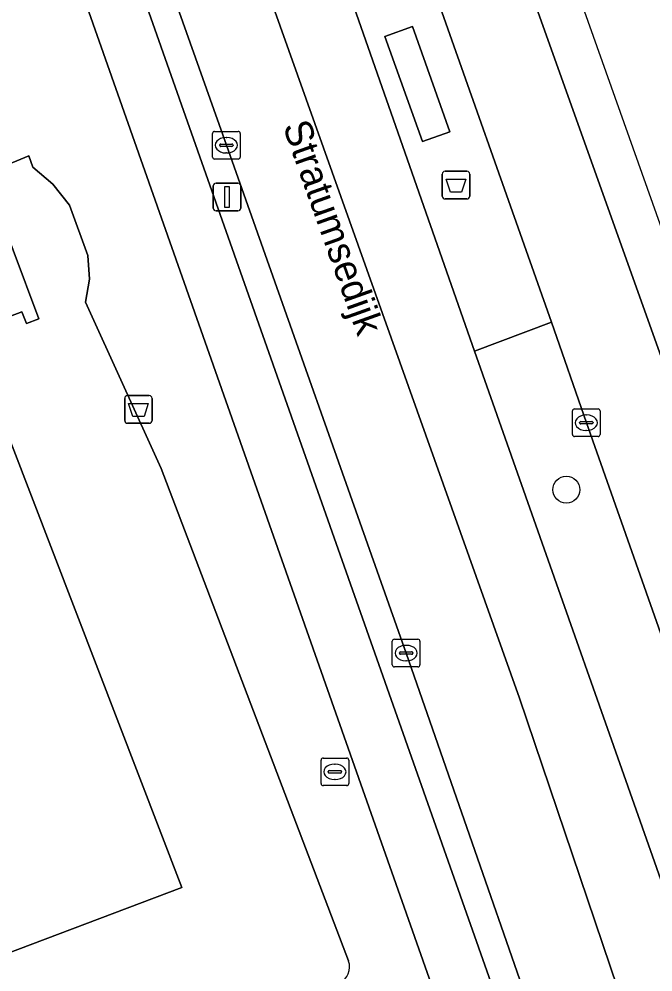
# Model space of a CAD drawing. Extents: x 161347 to 161881, y 382161 to 382804.
# Drawn here: x 161789.84 to 161812.75, y 382511.92 to 382546.37 of the extents above; entities that cross this region are included whole.
import ezdxf

# ---------------------------------------------------------------- set-up
doc = ezdxf.new("R2010")
doc.units = 0
for name, color, linetype in [('IMGEO_Afvalbak', 7, 'Continuous'), ('IMGEO_Berm_groen', 7, 'Continuous'), ('IMGEO_Boom', 7, 'Continuous'), ('IMGEO_Brandkraan', 7, 'Continuous'), ('IMGEO_Erf', 7, 'Continuous'), ('IMGEO_Fietspad_gesloten', 7, 'Continuous'), ('IMGEO_Kolk', 7, 'Continuous'), ('IMGEO_Lichtmast', 7, 'Continuous'), ('IMGEO_Openbare_ruimte_label', 7, 'Continuous'), ('IMGEO_OVBaan_gesloten', 7, 'Continuous'), ('IMGEO_Pand', 7, 'Continuous'), ('IMGEO_Rijbaan_lokaal_gesloten', 7, 'Continuous'), ('IMGEO_Rijbaan_lokaal_open', 7, 'Continuous'), ('IMGEO_Verkeerseiland_open', 7, 'Continuous'), ('IMGEO_Voetpad_open', 7, 'Continuous')]:
    doc.layers.add(name, color=color, linetype=linetype)

msp = doc.modelspace()

# ---------------------------------------------------------------- linework, layer by layer
at = {"layer": 'IMGEO_Afvalbak'}
for p, q in [((161805.135, 382539.966), (161805.135, 382540.766)), ((161805.135, 382540.766), (161805.135, 382539.966)), ((161805.235, 382540.866), (161806.025, 382540.866)), ((161806.025, 382540.866), (161805.235, 382540.866)), ((161806.125, 382540.766), (161806.125, 382539.966)), ((161806.125, 382539.966), (161806.125, 382540.766)), ((161806.025, 382539.866), (161805.235, 382539.866)), ((161805.235, 382539.866), (161806.025, 382539.866)), ((161793.754, 382532.757), (161794.544, 382532.757)), ((161794.544, 382532.757), (161793.754, 382532.757)), ((161793.654, 382531.857), (161793.654, 382532.657)), ((161793.654, 382532.657), (161793.654, 382531.857)), ((161794.644, 382532.657), (161794.644, 382531.857)), ((161794.644, 382531.857), (161794.644, 382532.657)), ((161794.544, 382531.757), (161793.754, 382531.757)), ((161793.754, 382531.757), (161794.544, 382531.757))]:
    msp.add_line(p, q, dxfattribs=at)
for points in [[(161805.278, 382540.58), (161805.982, 382540.58), (161805.833, 382540.11), (161805.427, 382540.11), (161805.278, 382540.58)], [(161793.797, 382532.471), (161794.501, 382532.471), (161794.352, 382532.001), (161793.946, 382532.001), (161793.797, 382532.471)]]:
    msp.add_lwpolyline(points, dxfattribs=at)
for centre, start, end in [((161805.235, 382540.766), 90, 180), ((161805.235, 382540.766), 90, 180), ((161806.025, 382540.766), 0, 90), ((161806.025, 382540.766), 360, 90), ((161805.235, 382539.966), 180, 270), ((161805.235, 382539.966), 180, 270), ((161806.025, 382539.966), 270, 0), ((161806.025, 382539.966), 270, 0), ((161793.754, 382532.657), 90, 180), ((161793.754, 382532.657), 90, 180), ((161794.544, 382532.657), 0, 90), ((161794.544, 382532.657), 360, 90), ((161793.754, 382531.857), 180, 270), ((161793.754, 382531.857), 180, 270), ((161794.544, 382531.857), 270, 0), ((161794.544, 382531.857), 270, 0)]:
    msp.add_arc(centre, 0.1, start, end, dxfattribs=at)
at = {"layer": 'IMGEO_Berm_groen'}
msp.add_lwpolyline([(161838.414, 382445.861), (161832.947, 382463.543), (161827.474, 382481.211), (161827.11, 382482.403), (161824.596, 382490.14), (161822.084, 382497.878), (161821.393, 382500), (161816.691, 382513.676), (161816.31, 382514.849), (161810.342, 382531.777), (161809.081, 382535.415), (161806.297, 382534.364), (161814.219, 382511.898), (161817.462, 382502.267), (161818.198, 382499.999), (161826.049, 382475.724)], dxfattribs=at)
at = {"layer": 'IMGEO_Boom'}
msp.add_circle((161809.62, 382529.355), 0.489, dxfattribs=at)
at = {"layer": 'IMGEO_Brandkraan'}
for p, q in [((161800.752, 382518.731), (161800.752, 382519.583)), ((161800.827, 382519.657), (161801.679, 382519.657)), ((161801.753, 382519.583), (161801.753, 382518.731)), ((161801.24, 382519.437), (161801.265, 382519.437)), ((161801.011, 382519.151), (161801.011, 382519.163)), ((161801.449, 382519.114), (161801.051, 382519.114)), ((161801.054, 382519.2), (161801.452, 382519.2)), ((161801.495, 382519.163), (161801.495, 382519.151)), ((161801.679, 382518.657), (161800.827, 382518.657)), ((161801.263, 382518.877), (161801.238, 382518.877))]:
    msp.add_line(p, q, dxfattribs=at)
for points in [[(161800.752, 382518.731), (161800.752, 382519.583)], [(161800.827, 382519.657), (161801.679, 382519.657)], [(161801.753, 382519.583), (161801.753, 382518.731)], [(161801.679, 382518.657), (161800.827, 382518.657)]]:
    msp.add_lwpolyline(points, dxfattribs=at)
for centre, radius, start, end in [((161800.829, 382519.581), 0.0765, 91.552, 178.448), ((161800.829, 382519.581), 0.0765, 91.552, 178.448), ((161801.677, 382519.581), 0.0765, 1.552, 88.448), ((161801.677, 382519.581), 0.0765, 1.552, 88.448), ((161801.051, 382519.16), 0.0403, 85.8775, 175.7526), ((161801.048, 382519.15), 0.0366, 178.938, 274.7102), ((161801.452, 382519.157), 0.043, 264.8664, 352.4533), ((161801.456, 382519.162), 0.0386, 1.7309, 96.639), ((161800.829, 382518.733), 0.0765, 181.552, 268.448), ((161800.829, 382518.733), 0.0765, 181.552, 268.448), ((161801.677, 382518.733), 0.0765, 271.552, 358.448), ((161801.677, 382518.733), 0.0765, 271.552, 358.448)]:
    msp.add_arc(centre, radius, start, end, dxfattribs=at)
for centre, major_axis, ratio, start_param, end_param in [((161801.239, 382519.157), (-0.387, 0.002), 0.722429, 4.712389, 7.853982), ((161801.264, 382519.157), (-0.39, 0.002), 0.717154, 1.570796, 4.712389)]:
    msp.add_ellipse(centre, major_axis=major_axis, ratio=ratio, start_param=start_param, end_param=end_param, dxfattribs=at)
at = {"layer": 'IMGEO_Erf'}
for points in [[(161794.971, 382530.118), (161792.241, 382536.131), (161792.378, 382536.972), (161792.323, 382537.821), (161791.654, 382539.638), (161791.061, 382540.405), (161790.328, 382541.011), (161790.189, 382541.423), (161789.107, 382540.979), (161788.094, 382543.265), (161787.424, 382542.968), (161782.001, 382556.605), (161781.188, 382558.978), (161780.231, 382559.421), (161779.298, 382559.715), (161776.187, 382560.249), (161770.93, 382560.454), (161716.681, 382562.374), (161709.058, 382555.75), (161702.444, 382550.002), (161681.121, 382531.471), (161671.366, 382522.817), (161670.351, 382521.638), (161669.529, 382520.317)], [(161764.271, 382534.527), (161785.178, 382542.374), (161786.424, 382539.134), (161788.413, 382539.88), (161788.244, 382540.331), (161788.686, 382540.497), (161790.549, 382535.529), (161790.101, 382535.361), (161789.941, 382535.787), (161787.992, 382535.056), (161795.715, 382514.974), (161766.605, 382503.972)], [(161801.747, 382512.319), (161794.971, 382530.118)]]:
    msp.add_lwpolyline(points, dxfattribs=at)
msp.add_arc((161801.142, 382512.104), 0.641, 295.8327, 19.5454, dxfattribs=at)
at = {"layer": 'IMGEO_Fietspad_gesloten'}
msp.add_lwpolyline([(161810.816, 382500), (161809.536, 382504.029), (161791.875, 382554.154), (161791.037, 382556.261), (161789.046, 382556.024), (161804.957, 382510.847), (161807.409, 382503.909), (161808.2, 382501.628), (161808.681, 382500)], dxfattribs=at)
at = {"layer": 'IMGEO_Kolk'}
for p, q in [((161796.903, 382542.309), (161797.755, 382542.309)), ((161796.828, 382541.383), (161796.828, 382542.235)), ((161797.316, 382542.089), (161797.341, 382542.089)), ((161797.829, 382542.235), (161797.829, 382541.383)), ((161797.087, 382541.803), (161797.087, 382541.815)), ((161797.525, 382541.766), (161797.127, 382541.766)), ((161797.13, 382541.852), (161797.528, 382541.852)), ((161797.571, 382541.815), (161797.571, 382541.803)), ((161797.755, 382541.309), (161796.903, 382541.309)), ((161797.339, 382541.529), (161797.314, 382541.529)), ((161809.84, 382531.351), (161809.84, 382532.203)), ((161809.915, 382532.277), (161810.767, 382532.277)), ((161810.328, 382532.057), (161810.353, 382532.057)), ((161810.841, 382532.203), (161810.841, 382531.351)), ((161810.099, 382531.771), (161810.099, 382531.783)), ((161810.537, 382531.734), (161810.139, 382531.734)), ((161810.142, 382531.82), (161810.54, 382531.82)), ((161810.583, 382531.783), (161810.583, 382531.771)), ((161810.351, 382531.497), (161810.326, 382531.497)), ((161810.767, 382531.277), (161809.915, 382531.277)), ((161803.326, 382523.024), (161803.326, 382523.876)), ((161803.401, 382523.95), (161804.253, 382523.95)), ((161803.814, 382523.73), (161803.839, 382523.73)), ((161804.327, 382523.876), (161804.327, 382523.024)), ((161803.585, 382523.444), (161803.585, 382523.456)), ((161804.023, 382523.407), (161803.625, 382523.407)), ((161803.628, 382523.493), (161804.026, 382523.493)), ((161804.069, 382523.456), (161804.069, 382523.444)), ((161803.837, 382523.17), (161803.812, 382523.17)), ((161804.253, 382522.95), (161803.401, 382522.95))]:
    msp.add_line(p, q, dxfattribs=at)
for points in [[(161796.903, 382542.309), (161797.755, 382542.309)], [(161796.828, 382541.383), (161796.828, 382542.235)], [(161797.829, 382542.235), (161797.829, 382541.383)], [(161797.755, 382541.309), (161796.903, 382541.309)], [(161809.84, 382531.351), (161809.84, 382532.203)], [(161809.915, 382532.277), (161810.767, 382532.277)], [(161810.841, 382532.203), (161810.841, 382531.351)], [(161810.767, 382531.277), (161809.915, 382531.277)], [(161803.326, 382523.024), (161803.326, 382523.876)], [(161803.401, 382523.95), (161804.253, 382523.95)], [(161804.327, 382523.876), (161804.327, 382523.024)], [(161804.253, 382522.95), (161803.401, 382522.95)]]:
    msp.add_lwpolyline(points, dxfattribs=at)
for centre, radius, start, end in [((161796.905, 382542.233), 0.0765, 91.552, 178.448), ((161796.905, 382542.233), 0.0765, 91.552, 178.448), ((161797.753, 382542.233), 0.0765, 1.552, 88.448), ((161797.753, 382542.233), 0.0765, 1.552, 88.448), ((161797.127, 382541.812), 0.0403, 85.8775, 175.7526), ((161797.124, 382541.802), 0.0366, 178.938, 274.7102), ((161797.528, 382541.809), 0.043, 264.8664, 352.4533), ((161797.532, 382541.814), 0.0386, 1.7309, 96.639), ((161796.905, 382541.385), 0.0765, 181.552, 268.448), ((161796.905, 382541.385), 0.0765, 181.552, 268.448), ((161797.753, 382541.385), 0.0765, 271.552, 358.448), ((161797.753, 382541.385), 0.0765, 271.552, 358.448), ((161809.917, 382532.201), 0.0765, 91.552, 178.448), ((161809.917, 382532.201), 0.0765, 91.552, 178.448), ((161810.765, 382532.201), 0.0765, 1.552, 88.448), ((161810.765, 382532.201), 0.0765, 1.552, 88.448), ((161810.139, 382531.78), 0.0403, 85.8775, 175.7526), ((161810.136, 382531.77), 0.0366, 178.938, 274.7102), ((161810.54, 382531.777), 0.043, 264.8664, 352.4533), ((161810.544, 382531.782), 0.0386, 1.7309, 96.639), ((161809.917, 382531.353), 0.0765, 181.552, 268.448), ((161809.917, 382531.353), 0.0765, 181.552, 268.448), ((161810.765, 382531.353), 0.0765, 271.552, 358.448), ((161810.765, 382531.353), 0.0765, 271.552, 358.448), ((161803.403, 382523.874), 0.0765, 91.552, 178.448), ((161803.403, 382523.874), 0.0765, 91.552, 178.448), ((161804.251, 382523.874), 0.0765, 1.552, 88.448), ((161804.251, 382523.874), 0.0765, 1.552, 88.448), ((161803.625, 382523.453), 0.0403, 85.8775, 175.7526), ((161803.622, 382523.443), 0.0366, 178.938, 274.7102), ((161804.026, 382523.45), 0.043, 264.8664, 352.4533), ((161804.03, 382523.455), 0.0386, 1.7309, 96.639), ((161803.403, 382523.026), 0.0765, 181.552, 268.448), ((161803.403, 382523.026), 0.0765, 181.552, 268.448), ((161804.251, 382523.026), 0.0765, 271.552, 358.448), ((161804.251, 382523.026), 0.0765, 271.552, 358.448)]:
    msp.add_arc(centre, radius, start, end, dxfattribs=at)
for centre, major_axis, ratio, start_param, end_param in [((161797.315, 382541.809), (-0.387, 0.002), 0.722429, 4.712389, 7.853982), ((161797.34, 382541.809), (-0.39, 0.002), 0.717154, 1.570796, 4.712389), ((161810.327, 382531.777), (-0.387, 0.002), 0.722429, 4.712389, 7.853982), ((161810.352, 382531.777), (-0.39, 0.002), 0.717154, 1.570796, 4.712389), ((161803.813, 382523.45), (-0.387, 0.002), 0.722429, 4.712389, 7.853982), ((161803.838, 382523.45), (-0.39, 0.002), 0.717154, 1.570796, 4.712389)]:
    msp.add_ellipse(centre, major_axis=major_axis, ratio=ratio, start_param=start_param, end_param=end_param, dxfattribs=at)
at = {"layer": 'IMGEO_Lichtmast'}
for p, q in [((161796.857, 382539.537), (161796.857, 382540.337)), ((161796.857, 382540.337), (161796.857, 382539.537)), ((161796.957, 382540.437), (161797.747, 382540.437)), ((161797.747, 382540.437), (161796.957, 382540.437)), ((161797.847, 382540.337), (161797.847, 382539.537)), ((161797.847, 382539.537), (161797.847, 382540.337)), ((161797.747, 382539.437), (161796.957, 382539.437)), ((161796.957, 382539.437), (161797.747, 382539.437))]:
    msp.add_line(p, q, dxfattribs=at)
msp.add_lwpolyline([(161797.277, 382540.312), (161797.427, 382540.312), (161797.427, 382539.562), (161797.277, 382539.562), (161797.277, 382540.312)], dxfattribs=at)
for centre, start, end in [((161796.957, 382540.337), 90, 180), ((161796.957, 382540.337), 90, 180), ((161797.747, 382540.337), 0, 90), ((161797.747, 382540.337), 360, 90), ((161796.957, 382539.537), 180, 270), ((161796.957, 382539.537), 180, 270), ((161797.747, 382539.537), 270, 0), ((161797.747, 382539.537), 270, 0)]:
    msp.add_arc(centre, 0.1, start, end, dxfattribs=at)
at = {"layer": 'IMGEO_OVBaan_gesloten'}
for points in [[(161872.677, 382345.565), (161861.946, 382386.568), (161840.102, 382457.985), (161829.727, 382491.906), (161806.831, 382556.367), (161804.299, 382563.495), (161802.764, 382562.95), (161813.473, 382532.981), (161825.781, 382496.935), (161846.541, 382430.889), (161855.809, 382400.479), (161858.997, 382388.612), (161866.559, 382360.242), (161870.464, 382345.086), (161872.677, 382345.565)], [(161846.541, 382430.889), (161825.781, 382496.935), (161813.473, 382532.981), (161802.764, 382562.95), (161799.758, 382561.881), (161804.351, 382548.821), (161809.081, 382535.415), (161810.342, 382531.777), (161816.31, 382514.849), (161816.691, 382513.676), (161821.393, 382500), (161822.084, 382497.878), (161824.596, 382490.14), (161827.11, 382482.403), (161827.474, 382481.211), (161832.947, 382463.543)]]:
    msp.add_lwpolyline(points, dxfattribs=at)
at = {"layer": 'IMGEO_Pand'}
msp.add_lwpolyline([(161766.605, 382503.972), (161795.715, 382514.974), (161787.992, 382535.056), (161789.941, 382535.787), (161790.101, 382535.361), (161790.549, 382535.529), (161788.686, 382540.497), (161788.244, 382540.331), (161788.413, 382539.88), (161786.424, 382539.134), (161785.178, 382542.374), (161764.271, 382534.527)], dxfattribs=at)
at = {"layer": 'IMGEO_Rijbaan_lokaal_gesloten'}
for points in [[(161796.666, 382561.875), (161794.072, 382560.74), (161807.929, 382521.82), (161816.118, 382497.6), (161820.737, 382483.038), (161830.884, 382450.092), (161838.155, 382424.383), (161849.904, 382380.752), (161850.34, 382378.969), (161857.915, 382347.985), (161859.586, 382342.023), (161864.974, 382343.665), (161862.068, 382355.99), (161860.529, 382361.9), (161849.01, 382406.436), (161847.83, 382410.193)], [(161826.049, 382475.724), (161818.198, 382499.999), (161817.462, 382502.267), (161814.219, 382511.898), (161806.297, 382534.364), (161796.666, 382561.875)], [(161794.072, 382560.74), (161791.133, 382559.453), (161791.147, 382559.234), (161797.329, 382541.81), (161803.828, 382523.451), (161810.418, 382504.506), (161811.234, 382502.093), (161811.913, 382500), (161816.438, 382486.046), (161816.538, 382485.73)], [(161836.135, 382419.846), (161837.483, 382414.824), (161842.177, 382396.931), (161846.817, 382379.086), (161847.897, 382374.98), (161851.237, 382362.189), (161851.314, 382361.962), (161853.245, 382354.216), (161856.387, 382341.048), (161859.586, 382342.023), (161857.915, 382347.985), (161850.34, 382378.969), (161849.904, 382380.752), (161838.155, 382424.383), (161830.884, 382450.092), (161820.737, 382483.038), (161816.118, 382497.6), (161807.929, 382521.82), (161794.072, 382560.74)]]:
    msp.add_lwpolyline(points, dxfattribs=at)
at = {"layer": 'IMGEO_Rijbaan_lokaal_open'}
for points in [[(161809.081, 382535.415), (161804.351, 382548.821), (161799.758, 382561.881), (161799.395, 382562.865), (161796.666, 382561.875), (161806.297, 382534.364)], [(161804.416, 382541.943), (161803.063, 382545.735), (161804.057, 382546.1), (161805.411, 382542.293)]]:
    msp.add_lwpolyline(points, close=True, dxfattribs=at)
at = {"layer": 'IMGEO_Verkeerseiland_open'}
for points in [[(161812.938, 382484.988), (161816.438, 382486.046), (161811.913, 382500), (161811.234, 382502.093), (161810.418, 382504.506), (161803.828, 382523.451), (161797.329, 382541.81), (161791.147, 382559.234), (161791.133, 382559.453)], [(161789.934, 382559.058), (161791.037, 382556.261), (161791.875, 382554.154), (161809.536, 382504.029), (161810.816, 382500)]]:
    msp.add_lwpolyline(points, dxfattribs=at)
at = {"layer": 'IMGEO_Voetpad_open'}
for points in [[(161789.046, 382556.024), (161782.001, 382556.605), (161787.424, 382542.968), (161788.094, 382543.265), (161789.107, 382540.979), (161790.189, 382541.423), (161790.328, 382541.011), (161791.061, 382540.405), (161791.654, 382539.638), (161792.323, 382537.821), (161792.378, 382536.972), (161792.241, 382536.131), (161794.971, 382530.118), (161801.747, 382512.319)], [(161804.957, 382510.847), (161789.046, 382556.024)]]:
    msp.add_lwpolyline(points, dxfattribs=at)
msp.add_lwpolyline([(161805.411, 382542.293), (161804.057, 382546.1), (161803.063, 382545.735), (161804.416, 382541.943)], close=True, dxfattribs=at)
msp.add_arc((161801.142, 382512.104), 0.641, 295.8327, 19.5454, dxfattribs=at)

# ---------------------------------------------------------------- texts
at = {"layer": 'IMGEO_Openbare_ruimte_label'}
msp.add_text('Stratumsedijk', height=1, rotation=289.6307, dxfattribs=at).set_placement((161799.36, 382542.499))

doc.saveas('drawing.dxf')
